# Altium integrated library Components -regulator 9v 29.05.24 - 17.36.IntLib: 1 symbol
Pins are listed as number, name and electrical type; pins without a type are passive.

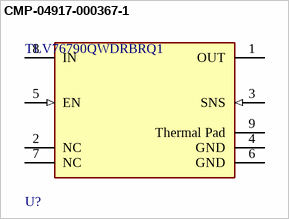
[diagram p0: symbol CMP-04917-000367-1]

## CMP-04917-000367-1
designator U?, comment TLV76790QWDRBRQ1
IC OPAMP
footprint FP-DRB0008J-IPC_C
footprint FP-DRB0008J-MFG
footprint FP-DRB0008J-IPC_A
footprint FP-DRB0008J-IPC_B
pins: 1 OUT, 2 NC, 3 SNS (in), 4 GND (power), 5 EN (in), 6 GND (power), 7 NC, 8 IN (power), 9 Thermal Pad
